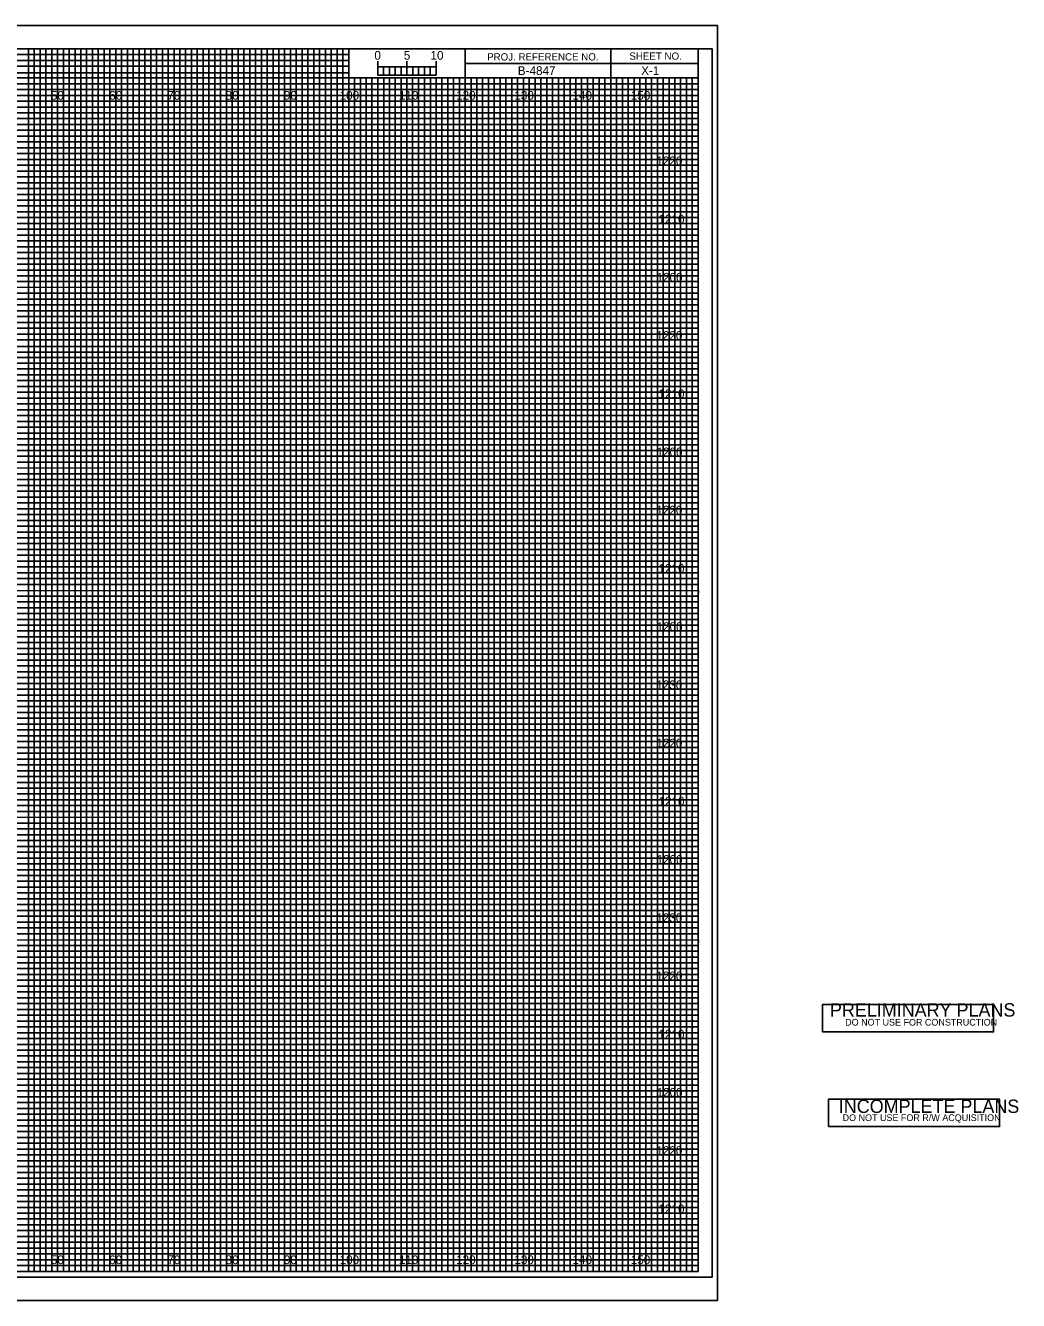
# Model space of a CAD drawing. Extents: x -13 to 375, y -5 to 214.
# Drawn here: x 204.5 to 375, y -5 to 214 of the extents above; entities that cross this region are included whole.
import ezdxf

# ---------------------------------------------------------------- set-up
doc = ezdxf.new("R2010")
doc.units = 0
for name, color, linetype in [('Prop XS Bar Scale Labels', 7, 'Continuous'), ('Prop XS Elevation Labels', 7, 'Continuous'), ('Prop XS Offset Labels', 7, 'Continuous'), ('Prop XS Project Number', 7, 'Continuous'), ('Prop XS Sheet Number', 7, 'Continuous'), ('Sheet Cross Section CELL', 7, 'Continuous'), ('Sheet Cross Section Grid Major CELL', 7, 'Continuous'), ('Sheet Cross Section Grid Middle CELL', 7, 'Continuous'), ('Sheet Cross Section Grid Minor 1 CELL', 7, 'Continuous'), ('Sheet Cross Section Grid Minor 2 CELL', 7, 'Continuous'), ('Sheet Cross Section Scale CELL', 7, 'Continuous'), ('Sheet Cutting Line CELL', 7, 'Continuous'), ('Sheet DOT Grid CELL', 7, 'Continuous'), ('Sheet Plot Border Inside CELL', 7, 'Continuous'), ('Sheet Plot Border Outside CELL', 7, 'Continuous'), ('Sheet Sticker Incomplete CELL', 7, 'Continuous'), ('Sheet Sticker Preliminary CELL', 7, 'Continuous')]:
    doc.layers.add(name, color=color, linetype=linetype)

msp = doc.modelspace()

# ---------------------------------------------------------------- linework, layer by layer
at = {"layer": 'Sheet Cross Section CELL'}
for p, q in [((305, 210), (305, 205)), ((305, 205), (305, 210)), ((280, 207.5), (280, 205)), ((320, 207.49), (280, 207.49)), ((280, 205), (320, 205))]:
    msp.add_line(p, q, dxfattribs=at)
for points in [[(320, 210), (0, 210), (0, 0), (320, 0)], [(280, 210), (260, 210), (260, 205.03), (280, 205.03)], [(320, 210), (280, 210), (280, 205), (320, 205)]]:
    msp.add_lwpolyline(points, close=True, dxfattribs=at)
at = {"layer": 'Sheet Cross Section Grid Major CELL'}
for p, q in [((210, 210), (200, 210)), ((210, 0), (210, 210)), ((230, 210), (220, 210)), ((220, 210), (220, 0)), ((230, 0), (230, 210)), ((250, 210), (240, 210)), ((240, 210), (240, 0)), ((250, 0), (250, 210)), ((260, 210), (260, 0)), ((270, 0), (270, 205)), ((290, 205), (280, 205)), ((280, 205), (280, 0)), ((290, 0), (290, 205)), ((310, 205), (300, 205)), ((300, 205), (300, 0)), ((310, 0), (310, 205)), ((220, 0), (210, 0)), ((240, 0), (230, 0)), ((260, 0), (250, 0)), ((280, 0), (270, 0)), ((300, 0), (290, 0)), ((320, 0), (310, 0)), ((320, 0), (320, 0))]:
    msp.add_line(p, q, dxfattribs=at)
for points in [[(0, 200), (320, 200), (320, 190), (0, 190)], [(0, 180), (320, 180), (320, 170), (0, 170)], [(0, 160), (320, 160), (320, 150), (0, 150)], [(0, 140), (320, 140), (320, 130), (0, 130)], [(0, 120), (320, 120), (320, 110), (0, 110)], [(0, 100), (320, 100), (320, 90), (0, 90)], [(0, 80), (320, 80), (320, 70), (0, 70)], [(0, 60), (320, 60), (320, 50), (0, 50)], [(0, 40), (320, 40), (320, 30), (0, 30)], [(0, 20), (320, 20), (320, 10), (0, 10)]]:
    msp.add_lwpolyline(points, dxfattribs=at)
at = {"layer": 'Sheet Cross Section Grid Middle CELL'}
for points in [[(195, 210), (205, 210), (205, 0), (215, 0), (215, 210), (225, 210), (225, 0), (235, 0), (235, 210), (245, 210), (245, 0), (255, 0), (255, 210), (259.93, 210), (260, 210), (260, 205), (264.99, 205), (264.99, 0), (275, 0), (275, 205), (285, 205), (285, 0), (295, 0), (295, 205), (305, 205), (305, 0), (315, 0), (315, 205)], [(0, 205), (275, 205)], [(0, 185), (320, 185), (320, 195), (0, 195)], [(0, 165), (320, 165), (320, 175), (0, 175)], [(0, 145), (320, 145), (320, 155), (0, 155)], [(0, 125), (320, 125), (320, 135), (0, 135)], [(0, 105), (320, 105), (320, 115), (0, 115)], [(0, 85), (320, 85), (320, 95), (0, 95)], [(0, 65), (320, 65), (320, 75), (0, 75)], [(0, 45), (320, 45), (320, 55), (0, 55)], [(0, 25), (320, 25), (320, 35), (0, 35)], [(0, 5), (320, 5), (320, 15), (0, 15)]]:
    msp.add_lwpolyline(points, dxfattribs=at)
at = {"layer": 'Sheet Cross Section Grid Minor 1 CELL'}
for p, q in [((0, 209), (260, 209)), ((260, 209), (260, 207.98)), ((260, 207.98), (0, 207.98)), ((0, 207), (260, 207)), ((260, 205.89), (0, 205.89)), ((260, 207), (260, 205.89)), ((0, 204), (320, 204))]:
    msp.add_line(p, q, dxfattribs=at)
for points in [[(0, 203), (270, 203), (320, 203), (320, 202), (0, 202)], [(0, 201), (320, 201), (320, 199), (0, 199)], [(0, 198), (320, 198), (320, 197), (0, 196.98)], [(0, 196), (320, 196), (320, 194), (0, 194)], [(0, 193), (320, 193), (320, 192), (0, 192)], [(0, 191), (320, 191), (320, 189), (0, 189)], [(0, 188), (320, 188), (320, 187), (0, 187)], [(0, 186), (320, 186), (320, 184), (0, 184)], [(0, 183), (320, 183), (320, 182), (0, 182)], [(0, 181), (320, 181), (320, 179), (0, 179)], [(0, 178), (320, 178), (320, 177), (0, 177)], [(0, 176), (320, 176), (320, 173.95), (320, 173), (320, 172), (0, 172)], [(0, 174), (320, 174), (320, 173), (0, 173)], [(0, 171), (320, 171), (320, 169), (0, 169.03)], [(0, 169.03), (320, 169), (320, 168), (0, 168)], [(0, 167), (320, 167), (320, 166), (0, 166)], [(0, 164), (320, 164), (320, 163), (0, 163)], [(0, 162), (320, 162), (320, 161), (0, 161)], [(-0.07, 158.89), (320, 158.89), (320, 157.88), (-0.07, 157.88)], [(0, 157), (320, 157), (320, 156), (0, 156)], [(0, 154), (320, 154), (320, 153), (0, 153)], [(0, 152), (320, 152), (320, 151), (0, 151)], [(0, 149), (320, 149), (320, 148), (0, 148)], [(0, 147), (320, 147), (320, 146), (0, 146)], [(0, 144), (320, 144), (320, 143), (0, 143)], [(0, 142), (320, 142), (320, 141), (0, 141)], [(0, 139), (320, 139), (319.99, 137.98), (0, 138)], [(0, 137), (320, 137), (320, 136), (0, 136)], [(0, 134), (320, 134), (320, 133), (0, 133)], [(0, 132), (320, 132), (320, 131), (0, 131)], [(0, 129), (320, 129), (320, 128), (0, 128)], [(0, 127), (320, 127), (320, 126), (0, 126)], [(0, 124), (320, 124), (320, 123), (0, 123)], [(0, 122), (320, 122), (320, 121), (0, 121)], [(0, 119), (320, 119), (320, 118), (0, 118)], [(0, 116.99), (320.07, 116.91), (320, 116), (0, 116)], [(0, 114), (320, 114), (320, 113), (0, 113)], [(0, 112), (320, 112), (320, 111), (0, 111)], [(0, 109), (320, 109), (320, 108), (0, 108)], [(0, 107), (320, 107), (320, 106), (0, 106)], [(0, 104), (320, 104), (320, 103), (0, 103)], [(0, 102), (320, 102), (320, 101), (0, 101)], [(0, 99), (320, 99), (320, 98), (0, 98)], [(0, 97), (320, 97), (320, 96), (0, 96)], [(0, 94), (320, 94), (320, 93), (0, 93)], [(0, 92), (320, 92), (320, 91), (0, 91)], [(0, 89), (320, 89), (320, 88), (0, 88)], [(0, 87), (320, 87), (320, 86), (0, 86)], [(0, 84), (320, 84), (320, 83), (0, 83)], [(0, 82), (320, 82), (320, 81), (0, 81)], [(0, 79), (320, 79), (319.99, 77.98), (0, 78)], [(0, 77), (320, 77), (320, 76), (0, 76)], [(0, 74), (320, 74), (320, 73), (0, 73)], [(0, 72), (320, 72), (320, 71), (0, 71)], [(0, 69), (320, 69), (320, 68), (0, 68)], [(0, 67), (320, 67), (320, 66), (0, 66)], [(0, 64), (320, 64), (320, 63), (0, 63)], [(0, 62), (320, 62), (320, 61), (0, 61)], [(0, 59), (320, 59), (320, 58), (0, 58)], [(0, 56.99), (320.07, 56.91), (320, 56), (0, 56)], [(0, 54), (320, 54), (320, 53), (0, 53)], [(0, 52), (320, 52), (320, 51), (0, 51)], [(0, 49), (320, 49), (320, 48), (0, 48)], [(0, 47), (320, 47), (320, 46), (0, 46)], [(0, 44), (320, 44), (320, 43), (0, 43)], [(0, 42), (320, 42), (320, 41), (0, 41)], [(0, 39), (320, 39), (320, 38), (0, 38)], [(0, 37), (320, 37), (320, 36), (0, 36)], [(0, 34), (320, 34), (320, 33), (0, 33)], [(0, 32), (320, 32), (320, 31), (0, 31)], [(0, 29), (320, 29), (320, 28), (0, 28)], [(0, 27), (320, 27), (320, 26), (0, 26)], [(0, 24), (320, 24), (320, 23), (0, 23)], [(0, 22), (320, 22), (320, 21), (0, 21)], [(0, 19), (320, 19), (320, 18), (0, 18)], [(0, 17), (320, 17), (320, 16), (0, 16)], [(0, 14), (320, 14), (320, 13), (0, 13)], [(0, 12), (320, 12), (320, 11), (0, 11)], [(0, 9), (320, 9), (320, 8), (0, 8)], [(0, 7), (320, 7), (320, 6), (0, 6)], [(0, 4), (320, 4), (320, 3), (0, 3)], [(0, 2), (320, 2), (320, 1), (0, 1)]]:
    msp.add_lwpolyline(points, dxfattribs=at)
at = {"layer": 'Sheet Cross Section Grid Minor 2 CELL'}
for p, q in [((267, 205), (266.01, 205)), ((266.01, 205), (266.01, 0)), ((267, 0), (267, 205)), ((269, 205), (268, 205)), ((268, 205), (268, 0)), ((269, 0), (269, 205)), ((266.01, 0), (265, 0)), ((268, 0), (267, 0))]:
    msp.add_line(p, q, dxfattribs=at)
for points in [[(205, 0), (206, 0), (206, 210), (207, 210), (207, 0)], [(207, 0), (208, 0), (208, 210), (209, 210), (209, 0)], [(210, 0), (211, 0), (211, 210), (212, 210), (212, 0)], [(212, 0), (213, 0), (213, 210), (214, 210), (214, 0)], [(215, 0), (216, 0), (216, 210), (217, 210), (217, 0)], [(217, 0), (218, 0), (218, 210), (219, 210), (219, 0)], [(220, 0), (221, 0), (221, 210), (222, 210), (222, 0)], [(222, 0), (223, 0), (223, 210), (224, 210), (224, 0)], [(225, 0), (226, 0), (226, 210), (227, 210), (227, 0)], [(227, 0), (228, 0), (228, 210), (229, 210), (229, 0)], [(230, 0), (231, 0), (231, 210), (232, 210), (232, 0)], [(232, 0), (233, 0), (233, 210), (234, 210), (234, 0)], [(235, 0), (236, 0), (236, 210), (237, 210), (237, 0)], [(237, 0), (238, 0), (238, 210), (239, 210), (239, 0)], [(240, 0), (241, 0), (241, 210), (242, 210), (242, 0)], [(242, 0), (243, 0), (243, 210), (244, 210), (244, 0)], [(245, 0), (246, 0), (246, 210), (247, 210), (247, 0)], [(247, 0), (248, 0), (248, 210), (249, 210), (249, 0)], [(250, 0), (251, 0), (251, 210), (252, 210), (252, 0)], [(252, 0), (253, 0), (253, 210), (254, 210), (254, 0)], [(255, 0), (256, 0), (256, 210), (257, 210), (257, 0)], [(257, 0), (258, 0), (258, 210), (259, 210), (259, 0)], [(260, 0), (261, 0), (261, 205), (262.02, 205), (262.02, 0)], [(262, 0), (263, 0), (263, 205), (263.99, 205), (263.99, 0)], [(270, 0), (270.98, 0), (270.98, 205), (272, 205), (272, 0)], [(272, 0), (273, 0), (273, 205), (274.05, 205), (274.05, 0)], [(275, 0), (276, 0), (276, 205), (277, 205), (277, 0)], [(277, 0), (278, 0), (278, 205), (279, 205), (279, 0)], [(280, 0), (281, 0), (281, 205), (282, 205), (282, 0)], [(282, 0), (283, 0), (283, 205), (284, 205), (284, 0)], [(285, 0), (286, 0), (286, 205), (287, 205), (287, 0)], [(287, 0), (288, 0), (288, 205), (289, 205), (289, 0)], [(290, 0), (291, 0), (291, 205), (292, 205), (292, 0)], [(292, 0), (293, 0), (293, 205), (294, 205), (294, 0)], [(295, 0), (296, 0), (296, 205), (297, 205), (297, 0)], [(297, 0), (298, 0), (298, 205), (299, 205), (299, 0)], [(300, 0), (301, 0), (301, 205), (302, 205), (302, 0)], [(302, 0), (303, 0), (303, 205), (304, 205), (304, 0)], [(305, 0), (306, 0), (306, 205), (307, 205), (307, 0)], [(307, 0), (308, 0), (308, 205), (309, 205), (309, 0)], [(310, 0), (311, 0), (311, 205), (312, 205), (312, 0)], [(312, 0), (313, 0), (313, 205), (314, 205), (314, 0)], [(315, 0), (316, 0), (316, 205), (317, 205), (317, 0)], [(317, 0), (318, 0), (318, 205), (319, 205), (319, 0)]]:
    msp.add_lwpolyline(points, dxfattribs=at)
at = {"layer": 'Sheet Cross Section Scale CELL'}
for p, q in [((265, 205.49), (265, 207.9)), ((265, 206.9), (265, 207.9)), ((270, 205.49), (270, 207.9)), ((275, 205.49), (275, 207.9)), ((275, 206.9), (275, 207.9))]:
    msp.add_line(p, q, dxfattribs=at)
for points in [[(275, 206.9), (265, 206.9), (265, 205.49), (275, 205.49)], [(265, 206.9), (266, 206.9), (266, 205.49), (265, 205.49)], [(267, 206.9), (268, 206.9), (268, 205.49), (267, 205.49)], [(269, 206.9), (270, 206.9), (270, 205.49), (269, 205.49)], [(271, 206.9), (272, 206.9), (272, 205.49), (271, 205.49)], [(273, 206.9), (274, 206.9), (274, 205.49), (273, 205.49)]]:
    msp.add_lwpolyline(points, close=True, dxfattribs=at)
at = {"layer": 'Sheet Cutting Line CELL'}
for p, q in [((323.3, 214), (-13.4, 214)), ((-13.4, -5), (323.3, -5))]:
    msp.add_line(p, q, dxfattribs=at)
at = {"layer": 'Sheet DOT Grid CELL'}
for p, q in [((210, 0), (210, 210)), ((220, 0), (220, 210)), ((230, 0), (230, 210)), ((240, 0), (240, 210)), ((250, 0), (250, 210)), ((260, 0), (260, 204.69)), ((270, 0), (270, 204.69)), ((280, 0), (280, 204.69)), ((290, 0), (290, 204.69)), ((300, 0), (300, 204.69)), ((310, 0), (310, 204.69)), ((0, 200), (320, 200)), ((0, 190), (320, 190)), ((0, 180), (320, 180)), ((0, 170), (320, 170)), ((0, 160), (320, 160)), ((0, 150), (320, 150)), ((0, 140), (320, 140)), ((0, 130), (320, 130)), ((0, 120), (320, 120)), ((0, 110), (320, 110)), ((0, 100), (320, 100)), ((0, 90), (320, 90)), ((0, 80), (320, 80)), ((0, 70), (320, 70)), ((0, 60), (320, 60)), ((0, 50), (320, 50)), ((0, 40), (320, 40)), ((0, 30), (320, 30)), ((0, 20), (320, 20)), ((0, 10), (320, 10))]:
    msp.add_line(p, q, dxfattribs=at)
at = {"layer": 'Sheet Plot Border Inside CELL'}
msp.add_lwpolyline([(-10.8, -1), (322.4, -1), (322.4, 210), (-10.8, 210)], close=True, dxfattribs=at)
at = {"layer": 'Sheet Plot Border Outside CELL'}
msp.add_lwpolyline([(-13.4, -5), (323.3, -5), (323.3, 214), (-13.4, 214)], close=True, dxfattribs=at)
at = {"layer": 'Sheet Sticker Incomplete CELL'}
msp.add_lwpolyline([(342.37, 24.87), (342.37, 29.57), (371.77, 29.57), (371.77, 24.87)], close=True, dxfattribs=at)
at = {"layer": 'Sheet Sticker Preliminary CELL'}
msp.add_lwpolyline([(341.33, 41.13), (341.33, 45.83), (370.73, 45.83), (370.73, 41.13)], close=True, dxfattribs=at)

# ---------------------------------------------------------------- texts
at = {"layer": 'Prop XS Bar Scale Labels'}
for s, p in [('5', (269.47, 208.12)), ('10', (274.04, 208.12))]:
    msp.add_text(s, height=1.5, dxfattribs=at).set_placement(p)
at = {"layer": 'Prop XS Elevation Labels'}
for s, p in [('1220', (312.83, 190)), ('1210', (313.2, 180)), ('1200', (312.87, 170)), ('1220', (312.83, 160)), ('1210', (313.2, 150)), ('1200', (312.87, 140)), ('1220', (312.83, 130)), ('1210', (313.2, 120)), ('1200', (312.87, 110)), ('1230', (312.82, 100)), ('1220', (312.83, 90)), ('1210', (313.2, 80)), ('1200', (312.87, 70)), ('1230', (312.82, 60)), ('1220', (312.83, 50)), ('1210', (313.2, 40)), ('1200', (312.87, 30)), ('1220', (312.83, 20)), ('1210', (313.2, 10))]:
    msp.add_text(s, height=1.5, dxfattribs=at).set_placement(p)
at = {"layer": 'Prop XS Offset Labels'}
for s, p in [('50', (208.86, 201.25)), ('60', (218.86, 201.25)), ('70', (228.86, 201.25)), ('80', (238.86, 201.25)), ('90', (248.86, 201.25)), ('100', (258.44, 201.25)), ('110', (268.62, 201.25)), ('120', (278.44, 201.25)), ('130', (288.44, 201.25)), ('140', (298.44, 201.25)), ('150', (308.44, 201.25)), ('50', (208.86, 1.25)), ('60', (218.86, 1.25)), ('70', (228.86, 1.25)), ('80', (238.86, 1.25)), ('90', (248.86, 1.25)), ('100', (258.44, 1.25)), ('110', (268.62, 1.25)), ('120', (278.44, 1.25)), ('130', (288.44, 1.25)), ('140', (298.44, 1.25)), ('150', (308.44, 1.25))]:
    msp.add_text(s, height=1.5, dxfattribs=at).set_placement(p)
at = {"layer": 'Prop XS Project Number'}
msp.add_text('B-4847', height=1.5, dxfattribs=at).set_placement((289.04, 205.5))
at = {"layer": 'Prop XS Sheet Number'}
msp.add_text('X-1', height=1.5, dxfattribs=at).set_placement((310.22, 205.5))
at = {"layer": 'Sheet Cross Section CELL'}
for s, p in [('PROJ. REFERENCE NO.', (283.77, 207.99)), ('SHEET NO.', (308.19, 208.12))]:
    msp.add_text(s, height=1.25, dxfattribs=at).set_placement(p)
at = {"layer": 'Sheet Cross Section Scale CELL'}
msp.add_text('0', height=1.5, dxfattribs=at).set_placement((264.41, 208.12))
at = {"layer": 'Sheet Sticker Incomplete CELL'}
for s, height, p in [('INCOMPLETE PLANS', 2.304, (344.16, 27.21)), ('DO NOT USE FOR R/W ACQUISITION', 1.152, (344.81, 25.82))]:
    msp.add_text(s, height=height, dxfattribs=at).set_placement(p)
at = {"layer": 'Sheet Sticker Preliminary CELL'}
for s, height, p in [('PRELIMINARY PLANS', 2.304, (342.63, 43.76)), ('DO NOT USE FOR CONSTRUCTION', 1.152, (345.25, 42.22))]:
    msp.add_text(s, height=height, dxfattribs=at).set_placement(p)

doc.saveas('drawing.dxf')
